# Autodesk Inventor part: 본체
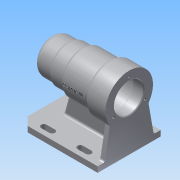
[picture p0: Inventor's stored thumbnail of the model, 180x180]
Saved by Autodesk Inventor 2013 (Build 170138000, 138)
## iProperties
Created: 2017-09
Part Number: 본체
Material: 알루미늄 6061
Document SubType Name: Modeling
Designer: Administrator
Mass: 702.292 g
Surface Area: 713.068 cm^2
Volume: 259.148 cm^3
Density: 2.71 g/cm^3
Author: Administrator
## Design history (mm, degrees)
node "스케치1"
sketch "스케치2"
  geometry: C1 r 34 at (0, 0); 1 further point
  constraints: 1 centre point, 1 coincident
  dimensions: "d15" = 68 diameter of C1
extrude "돌출1" new body sketch "스케치2" distance "d17" = 28; taper "d18" = 0 deg
sketch "스케치3"
  geometry: C1 r 34 at (0, 0) reference; C2 r 30 at (0, 0)
  constraints: 1 centre point, 1 coincident
  dimensions: "d19" = 60 diameter of C2
extrude "돌출2" join sketch "스케치3" distance "d21" = 39; taper "d22" = 0 deg
sketch "스케치4"
  geometry: C1 r 30 at (0, 0) reference; C2 r 27 at (0, 0)
  constraints: 1 centre point, 1 coincident
  dimensions: "d23" = 54 diameter of C2
extrude "돌출3" join sketch "스케치4" distance "d25" = 20; taper "d26" = 0 deg
sketch "스케치5"
  geometry: C1 r 27 at (0, 0) reference; C2 r 25 at (0, 0)
  constraints: 1 centre point, 1 coincident
  dimensions: "d27" = 50 diameter of C2
extrude "돌출4" join sketch "스케치5" distance "d29" = 25; taper "d30" = 0 deg
sketch "스케치6"
  geometry: C1 r 34 at (0, 0) reference; 1 further point
  constraints: 1 coincident
hole "구멍1" sketch "스케치6" at (0, 0) diameter "d31" = 42; stored, may be unused: countersink angle "d35" = 90 deg, drill point angle "d37" = 0 deg; dims "d32" = 6, "d33" = 42, "d34" = 15, "d36" = 15
sketch "스케치7"
  geometry: C1 r 21 at (0, 0) reference
sketch "스케치8"
  geometry: C1 r 21 at (0, 0) reference; C2 r 24 at (0, 0)
  constraints: 2 coincident, 1 centre point
  dimensions: "d38" = 48 diameter of C2
extrude "돌출5" cut sketch "스케치8" distance "d40" = 54; taper "d41" = 0 deg
sketch "스케치9"
  geometry: C1 r 24 at (0, 0) reference; C2 r 21 at (0, 0)
  constraints: 1 centre point, 1 coincident
  dimensions: "d42" = 42 diameter of C2
extrude "돌출6" cut sketch "스케치9" distance "d44" = 12; taper "d45" = 0 deg
sketch "스케치10"
  geometry: C1 r 21 at (0, 0) reference; C2 r 17.5 at (0, 0)
  constraints: 1 centre point, 1 coincident
  dimensions: "d46" = 35 diameter of C2
extrude "돌출7" cut sketch "스케치10" distance "d48" = 18; taper "d49" = 0 deg
sketch "스케치11"
  geometry: C1 r 17.5 at (0, 0) reference; C2 r 16 at (0, 0)
  constraints: 1 centre point, 1 coincident
  dimensions: "d50" = 32 diameter of C2
extrude "돌출8" cut sketch "스케치11" distance "d52" = 4; taper "d53" = 0 deg
sketch "스케치12"
  geometry: C1 r 16 at (0, 0) reference; C2 r 10.5 at (0, 0)
  constraints: 1 centre point, 1 coincident
  dimensions: "d54" = 21 diameter of C2
extrude "돌출9" cut sketch "스케치12" distance "d56" = 3; taper "d57" = 0 deg
node "작업 평면1"
sketch "스케치13"
  geometry: L1 (84, -25)-(84, 25) reference; L2 (-28, 34)-(-28, -34) reference; L3 (84, -45)-(-28, -45); L4 (-28, -45)-(-28, 45); L5 (-28, 45)-(84, 45); L6 (84, 45)-(84, -45); 2 further points
  constraints: 8 end point, 2 midpoint, 2 parallel, 1 horizontal, 1 perpendicular
  dimensions: "d59" = 90 distance between parallel lines of L5 L3; "d61" = 112 distance between parallel lines of L4 L6
extrude "돌출10" join sketch "스케치13" distance "d62" = 8; taper "d63" = 0 deg
sketch "스케치14"
  geometry: L1 (28, -45)-(28, 45) reference; L2 (-8, -30)-(4, -30); L3 (4, -38)-(-8, -38); A1 r 4 centre (-8, -34) between (-8, -30) and (-8, -38); A2 r 4 centre (4, -34) between (4, -38) and (4, -30); 1 further point
  constraints: 4 end point, 4 point on circle, 4 tangent, 2 centre point, 1 horizontal, 1 parallel
  dimensions: "d66" = 12 distance of A2.centre A1.centre; "d68" = 4 radius of A2; "d70" = 24 distance from line of L1 A2.centre; "d71" = 34 vertical distance of point (0, 0) A2.centre
extrude "돌출11" cut sketch "스케치14" stored distance "d72" = 8; taper "d73" = 0 deg
chamfer "모따기1" distance "d77" = 12; stored, may be unused: second distance "d78" = 2, angle "d79" = 45 deg
sketch "스케치15"
  geometry: L1 (90, 0)-(0, 0) reference; L2 (0, 8)-(90, 8) reference; L3 (0, 0)-(0, 8) reference; L4 (17.425, 50.11)-(10, 8); L5 (10, 8)-(80, 8); L6 (45, 70)-(45, 0); L7 (72.575, 50.11)-(80, 8); C1 r 17.5 at (45, 70) reference; C2 r 30 at (45, 70) reference; 1 further point
  constraints: 8 end point, 2 perpendicular, 1 midpoint, 1 point on line, 1 other
  dimensions: "d80" = 10 distance from line of L4.end L3; "d82" = 100 deg angle of L2 L4; "d84" = 50.10971 distance from line of L7.start L1; "d85" = 50.10971 distance from line of L4.start L1
feature "리브1" sketch "스케치15" dims "d86" = 1, "d87" = 8, "d88" = 0, "d89" = 0, "d90" = 1, "d91" = 1
sketch "스케치16"
  geometry: L1 (-84, 33)-(-84, -33) reference; L2 (20, -35)-(20, 35) reference; L3 (20, 4)-(-62, 4); L4 (-62, 4)-(-62, -4); L5 (-62, -4)-(20, -4); L6 (20, -4)-(20, 4); 2 further points
  constraints: 8 end point, 2 midpoint, 2 parallel, 1 horizontal, 1 perpendicular, 1 point on line
  dimensions: "d92" = 8 distance between parallel lines of L5 L3; "d95" = 22 distance between parallel lines of L1 L4
extrude "돌출12" join sketch "스케치16" stored distance "d96" = 8; taper "d97" = 0 deg
feature "면 기울기1" dims angle "d98" = 15 deg
sketch "스케치18"
  geometry: C1 r 21 at (0, 0) reference; C2 r 1 at (0, 26)
  constraints: 1 centre point, 1 vertical alignment
  dimensions: "d102" = 26 distance of C1.centre C2.centre; "d103" = 2 diameter of C2
hole "구멍2" sketch "스케치18" at (0, 26) diameter "d104" = 3.242; stored, may be unused: countersink angle "d108" = 82 deg, drill point angle "d110" = 118 deg; dims "d105" = 8, "d106" = 3.023, "d107" = 15, "d109" = 11
chamfer "모따기2" distance "d114" = 1; stored, may be unused: second distance "d115" = 2, angle "d116" = 45 deg
fillet "모깎기1" dims "d117" = 3
fillet "모깎기2" dims "d118" = 3
fillet "모깎기3" dims "d119" = 0.3
fillet "모깎기4" dims "d120" = 9
fillet "모깎기5" dims "d121" = 3
fillet "모깎기6" dims "d122" = 3
fillet "모깎기7" dims "d123" = 3
fillet "모깎기8" dims "d124" = 3
fillet "모깎기9" dims "d125" = 3
fillet "모깎기10" dims "d126" = 3
node "작업 평면2"
sketch "스케치19"
  geometry: L1 (28, -18.917)-(28, 34) reference; 2 further points
  constraints: 1 horizontal alignment, 1 other
  dimensions: "d128" = 48 distance from line of point (-20, 0) L1
feature "엠보싱1" sketch "스케치19" dims "d29" = 25, "d129" = 0.5, "d130" = 0
node "솔리드1"
pattern_linear "직사각형 패턴1" dims "d76" = 52
mirror "대칭1"
pattern_circular "원형 패턴1" dims angle "d112" = 360 deg
